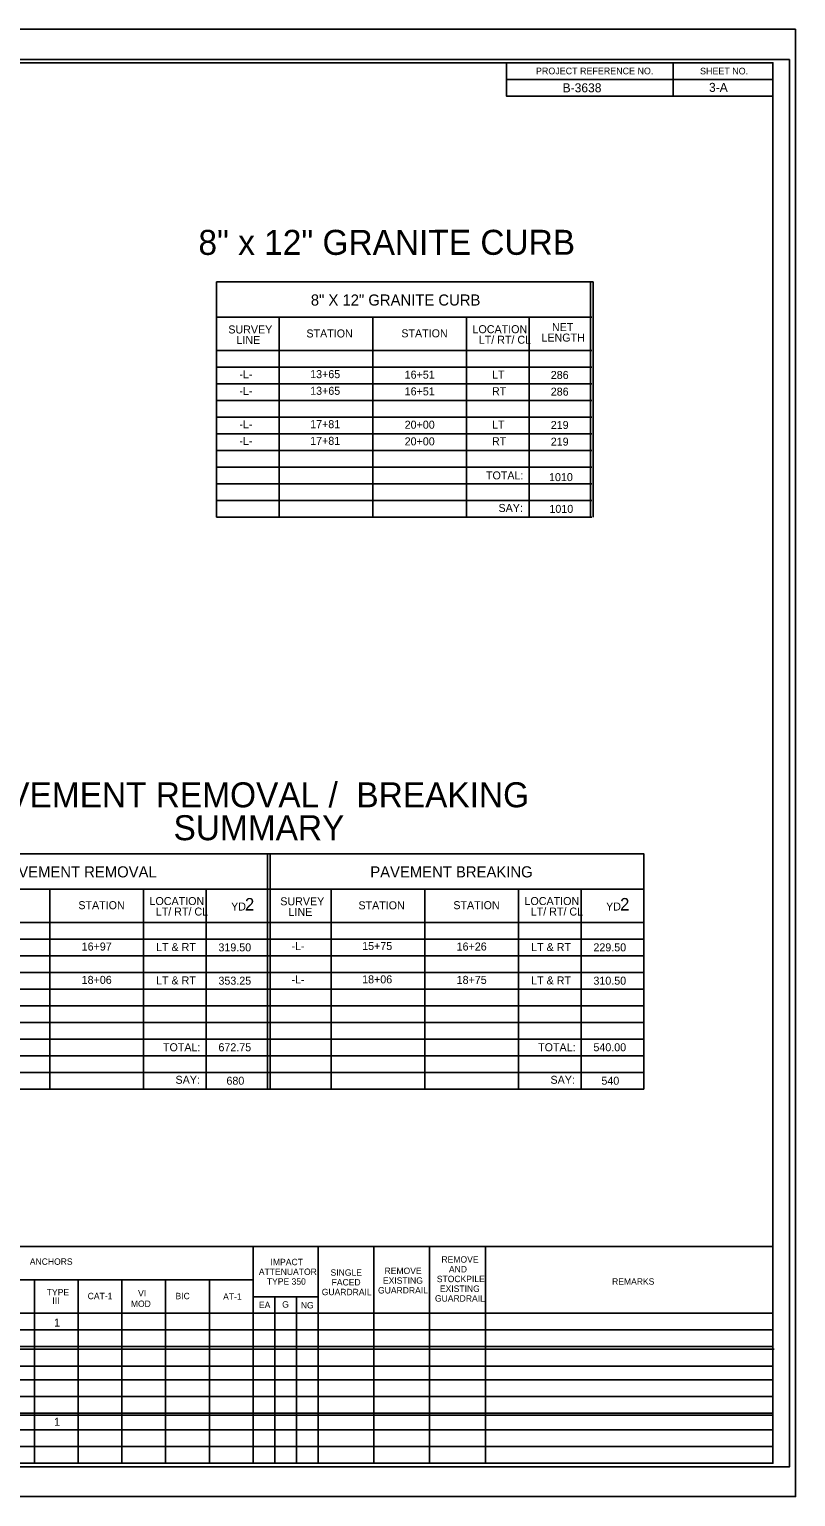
# Model space of a CAD drawing. Extents: x 1932260 to 1932428, y 647261 to 647371.
# Drawn here: x 1932370.6 to 1932428.1, y 647261 to 647371 of the extents above; entities that cross this region are included whole.
import ezdxf

# ---------------------------------------------------------------- set-up
doc = ezdxf.new("R2010")
doc.units = 0
for name, color, linetype in [('Sheet Cutting Line CELL', 7, 'Continuous'), ('Sheet Data Field CELL', 7, 'Continuous'), ('Sheet Plot Border Inside CELL', 7, 'Continuous'), ('Sheet Plot Border Outside CELL', 7, 'Continuous'), ('Sheet Summary Combination CELL', 7, 'Continuous'), ('Sheet Summary Combination Grid CELL', 7, 'Continuous'), ('Sheet Summary Earthwork CELL', 7, 'Continuous')]:
    doc.layers.add(name, color=color, linetype=linetype)

msp = doc.modelspace()

# ---------------------------------------------------------------- linework, layer by layer
at = {"layer": 'Sheet Cutting Line CELL'}
for p, q in [((1932428.13, 647371.04), (1932259.73, 647371.04)), ((1932259.73, 647261.04), (1932428.13, 647261.04))]:
    msp.add_line(p, q, dxfattribs=at)
at = {"layer": 'Sheet Plot Border Inside CELL'}
msp.add_lwpolyline([(1932427.68, 647368.79), (1932261.03, 647368.79), (1932261.03, 647263.28), (1932427.68, 647263.28)], close=True, dxfattribs=at)
at = {"layer": 'Sheet Plot Border Outside CELL'}
msp.add_lwpolyline([(1932428.13, 647371.04), (1932259.73, 647371.04), (1932259.73, 647261.04), (1932428.13, 647261.04)], close=True, dxfattribs=at)
at = {"layer": 'Sheet Summary Combination CELL'}
for p, q in [((1932428.13, 647371.04), (1932428.13, 647371.04)), ((1932427.68, 647368.79), (1932427.68, 647368.79)), ((1932398.82, 647349.46), (1932398.82, 647349.46)), ((1932399.44, 647349.45), (1932399.44, 647349.45)), ((1932400.35, 647349.47), (1932400.35, 647349.47)), ((1932400.91, 647349.46), (1932400.91, 647349.46)), ((1932374.59, 647306.59), (1932374.59, 647306.59)), ((1932375.21, 647306.58), (1932375.21, 647306.58)), ((1932376.12, 647306.6), (1932376.12, 647306.6)), ((1932376.68, 647306.59), (1932376.68, 647306.59)), ((1932402.72, 647306.59), (1932402.72, 647306.59)), ((1932403.35, 647306.58), (1932403.35, 647306.58)), ((1932404.25, 647306.6), (1932404.25, 647306.6)), ((1932404.81, 647306.59), (1932404.81, 647306.59))]:
    msp.add_line(p, q, dxfattribs=at)
at = {"layer": 'Sheet Summary Combination Grid CELL'}
for p, q in [((1932412.73, 647352.11), (1932412.73, 647334.46)), ((1932412.73, 647352.11), (1932412.93, 647352.11)), ((1932412.93, 647352.11), (1932412.93, 647334.46)), ((1932384.69, 647349.46), (1932412.83, 647349.46)), ((1932384.69, 647349.46), (1932384.69, 647334.46)), ((1932389.38, 647349.46), (1932389.38, 647334.46)), ((1932396.42, 647349.46), (1932396.42, 647334.46)), ((1932403.45, 647349.46), (1932403.45, 647334.46)), ((1932408.14, 647349.46), (1932408.14, 647334.46)), ((1932384.69, 647346.96), (1932412.83, 647346.96)), ((1932384.69, 647345.71), (1932412.83, 647345.71)), ((1932384.69, 647344.46), (1932412.83, 647344.46)), ((1932384.69, 647343.21), (1932412.83, 647343.21)), ((1932384.69, 647341.96), (1932412.83, 647341.96)), ((1932384.69, 647340.71), (1932412.83, 647340.71)), ((1932384.69, 647339.46), (1932412.83, 647339.46)), ((1932384.69, 647338.21), (1932412.83, 647338.21)), ((1932384.69, 647336.96), (1932412.83, 647336.96)), ((1932384.69, 647335.71), (1932412.83, 647335.71)), ((1932384.69, 647334.46), (1932412.83, 647334.46)), ((1932388.5, 647309.24), (1932388.5, 647291.59)), ((1932388.5, 647309.24), (1932388.7, 647309.24)), ((1932388.7, 647309.24), (1932388.7, 647291.59)), ((1932360.46, 647306.59), (1932388.6, 647306.59)), ((1932372.19, 647306.59), (1932372.19, 647291.59)), ((1932379.22, 647306.59), (1932379.22, 647291.59)), ((1932383.91, 647306.59), (1932383.91, 647291.59)), ((1932388.6, 647306.59), (1932416.73, 647306.59)), ((1932393.29, 647306.59), (1932393.29, 647291.59)), ((1932400.32, 647306.59), (1932400.32, 647291.59)), ((1932407.35, 647306.59), (1932407.35, 647291.59)), ((1932412.04, 647306.59), (1932412.04, 647291.59)), ((1932416.73, 647306.59), (1932416.73, 647291.59)), ((1932360.46, 647304.09), (1932388.6, 647304.09)), ((1932388.6, 647304.09), (1932416.73, 647304.09)), ((1932360.46, 647302.84), (1932388.6, 647302.84)), ((1932388.6, 647302.84), (1932416.73, 647302.84)), ((1932360.46, 647301.59), (1932388.6, 647301.59)), ((1932388.6, 647301.59), (1932416.73, 647301.59)), ((1932360.46, 647300.34), (1932388.6, 647300.34)), ((1932388.6, 647300.34), (1932416.73, 647300.34)), ((1932360.46, 647299.09), (1932388.6, 647299.09)), ((1932388.6, 647299.09), (1932416.73, 647299.09)), ((1932360.46, 647297.84), (1932388.6, 647297.84)), ((1932388.6, 647297.84), (1932416.73, 647297.84)), ((1932360.46, 647296.59), (1932388.6, 647296.59)), ((1932388.6, 647296.59), (1932416.73, 647296.59)), ((1932360.46, 647295.34), (1932388.6, 647295.34)), ((1932388.6, 647295.34), (1932416.73, 647295.34)), ((1932360.46, 647294.09), (1932388.6, 647294.09)), ((1932388.6, 647294.09), (1932416.73, 647294.09)), ((1932360.46, 647292.84), (1932388.6, 647292.84)), ((1932388.6, 647292.84), (1932416.73, 647292.84)), ((1932360.46, 647291.59), (1932388.6, 647291.59)), ((1932388.6, 647291.59), (1932416.73, 647291.59)), ((1932276.43, 647279.79), (1932426.43, 647279.79)), ((1932387.43, 647279.79), (1932387.43, 647263.54)), ((1932392.31, 647279.79), (1932392.31, 647263.54)), ((1932396.49, 647279.79), (1932396.49, 647263.54)), ((1932400.67, 647279.79), (1932400.67, 647263.54)), ((1932404.86, 647279.79), (1932404.86, 647263.54)), ((1932387.43, 647277.29), (1932339.71, 647277.29)), ((1932371.02, 647277.29), (1932371.02, 647263.54)), ((1932374.3, 647277.29), (1932374.3, 647263.54)), ((1932377.58, 647277.29), (1932377.58, 647263.54)), ((1932380.87, 647277.29), (1932380.87, 647263.54)), ((1932384.15, 647277.29), (1932384.15, 647263.54)), ((1932387.43, 647276.01), (1932392.29, 647276.01)), ((1932389.05, 647276.01), (1932389.06, 647263.54)), ((1932390.69, 647276.01), (1932390.69, 647263.54)), ((1932276.43, 647274.79), (1932426.43, 647274.79)), ((1932276.43, 647273.54), (1932426.43, 647273.54)), ((1932276.43, 647272.29), (1932426.43, 647272.29)), ((1932276.51, 647272.09), (1932426.51, 647272.09)), ((1932276.43, 647270.83), (1932426.43, 647270.83)), ((1932276.43, 647269.79), (1932426.43, 647269.79)), ((1932276.43, 647268.54), (1932426.43, 647268.54)), ((1932276.43, 647267.29), (1932426.43, 647267.29)), ((1932276.43, 647267.14), (1932426.43, 647267.14)), ((1932276.43, 647266.04), (1932426.43, 647266.04)), ((1932276.43, 647264.79), (1932426.43, 647264.79))]:
    msp.add_line(p, q, dxfattribs=at)
for points in [[(1932412.73, 647349.46), (1932384.69, 647349.46), (1932384.69, 647352.11), (1932412.73, 647352.11)], [(1932388.5, 647306.59), (1932360.46, 647306.59), (1932360.46, 647309.24), (1932388.5, 647309.24)], [(1932416.73, 647306.59), (1932388.7, 647306.59), (1932388.7, 647309.24), (1932416.73, 647309.24)]]:
    msp.add_lwpolyline(points, close=True, dxfattribs=at)
at = {"layer": 'Sheet Summary Earthwork CELL'}
for p, q in [((1932418.93, 647368.53), (1932418.93, 647366.03)), ((1932406.43, 647367.28), (1932426.43, 647367.28))]:
    msp.add_line(p, q, dxfattribs=at)
for points in [[(1932426.43, 647368.54), (1932276.43, 647368.54), (1932276.43, 647263.54), (1932426.43, 647263.54)], [(1932406.43, 647368.54), (1932426.43, 647368.54), (1932426.43, 647366.03), (1932406.43, 647366.03)]]:
    msp.add_lwpolyline(points, close=True, dxfattribs=at)

# ---------------------------------------------------------------- texts
at = {"layer": 'Sheet Data Field CELL'}
for s, p in [('B-3638', (1932410.65, 647366.32)), ('3-A', (1932421.63, 647366.35))]:
    msp.add_text(s, height=0.675, dxfattribs=at).set_placement(p)
at = {"layer": 'Sheet Summary Combination CELL'}
for s, height, p in [('8" x 12" GRANITE CURB', 1.875, (1932383.33, 647354.13)), ('8" X 12" GRANITE CURB', 0.8319, (1932391.76, 647350.33)), ('PAVEMENT REMOVAL /  BREAKING', 1.875, (1932365.64, 647312.71)), ('SUMMARY', 1.875, (1932381.46, 647310.25)), ('PAVEMENT REMOVAL', 0.8319, (1932368.33, 647307.46)), ('PAVEMENT BREAKING', 0.8319, (1932396.22, 647307.46))]:
    msp.add_text(s, height=height, rotation=0.0119, dxfattribs=at).set_placement(p)
for s, height, p in [('SURVEY', 0.6, (1932385.57, 647348.24)), ('LINE', 0.6, (1932386.18, 647347.45)), ('STATION', 0.6, (1932391.43, 647347.94)), ('STATION', 0.6, (1932398.55, 647347.95)), ('LOCATION', 0.6, (1932403.89, 647348.26)), ('LT/ RT/ CL', 0.6, (1932404.36, 647347.47)), ('TOTAL:', 0.6, (1932404.9, 647337.3)), ('SAY:', 0.6, (1932405.84, 647334.86)), ('STATION', 0.6, (1932374.32, 647305.08)), ('LOCATION', 0.6, (1932379.66, 647305.39)), ('LT/ RT/ CL', 0.6, (1932380.13, 647304.6)), ('SURVEY', 0.6, (1932389.47, 647305.37)), ('LINE', 0.6, (1932390.09, 647304.58)), ('STATION', 0.6, (1932395.33, 647305.07)), ('STATION', 0.6, (1932402.45, 647305.08)), ('LOCATION', 0.6, (1932407.79, 647305.39)), ('LT/ RT/ CL', 0.6, (1932408.26, 647304.6)), ('TOTAL:', 0.6, (1932380.67, 647294.43)), ('TOTAL:', 0.6, (1932408.81, 647294.43)), ('SAY:', 0.6, (1932381.61, 647291.99)), ('SAY:', 0.6, (1932409.74, 647291.99)), ('ANCHORS', 0.48, (1932370.68, 647278.42)), ('IMPACT', 0.48, (1932388.74, 647278.39)), ('REMOVE', 0.48, (1932401.56, 647278.58)), ('ATTENUATOR', 0.48, (1932387.86, 647277.66)), ('TYPE 350', 0.48, (1932388.46, 647276.93)), ('SINGLE', 0.48, (1932393.24, 647277.6)), ('EXISTING', 0.48, (1932397.17, 647277)), ('REMOVE', 0.48, (1932397.29, 647277.73)), ('STOCKPILE', 0.48, (1932401.21, 647277.12)), ('AND', 0.48, (1932402.12, 647277.85)), ('REMARKS', 0.48, (1932414.36, 647276.93)), ('TYPE', 0.48, (1932371.95, 647276.12)), ('CAT-1', 0.48, (1932375.02, 647275.84)), ('VI', 0.48, (1932378.8, 647276.05)), ('BIC', 0.48, (1932381.61, 647275.84)), ('GUARDRAIL', 0.48, (1932392.58, 647276.14)), ('FACED', 0.48, (1932393.32, 647276.87)), ('GUARDRAIL', 0.48, (1932396.8, 647276.27)), ('EXISTING', 0.48, (1932401.44, 647276.39)), ('III', 0.48, (1932372.37, 647275.49)), ('MOD', 0.48, (1932378.26, 647275.26)), ('AT-1', 0.48, (1932385.18, 647275.8)), ('EA', 0.48, (1932387.87, 647275.17)), ('G', 0.48, (1932389.61, 647275.21)), ('NG', 0.48, (1932391.01, 647275.15)), ('GUARDRAIL', 0.48, (1932401.07, 647275.66))]:
    msp.add_text(s, height=height, dxfattribs=at).set_placement(p)
at = {"layer": 'Sheet Summary Combination Grid CELL'}
for s, height, p in [('NET', 0.6, (1932409.85, 647348.42)), ('LENGTH', 0.6, (1932409.06, 647347.63)), ('YD', 0.6, (1932385.78, 647304.98)), ('2', 0.938, (1932386.82, 647304.98)), ('YD', 0.6, (1932413.91, 647304.98)), ('2', 0.938, (1932414.96, 647304.98))]:
    msp.add_text(s, height=height, dxfattribs=at).set_placement(p)
at = {"layer": 'Sheet Summary Earthwork CELL'}
for s, height, p in [('PROJECT REFERENCE NO.', 0.5, (1932408.65, 647367.67)), ('SHEET NO.', 0.5, (1932420.96, 647367.66)), ('-L-', 0.6, (1932386.4, 647344.88)), ('13+65', 0.6, (1932391.71, 647344.89)), ('16+51', 0.6, (1932398.8, 647344.85)), ('LT', 0.6, (1932405.35, 647344.86)), ('286', 0.6, (1932409.76, 647344.83)), ('-L-', 0.6, (1932386.4, 647343.63)), ('13+65', 0.6, (1932391.71, 647343.64)), ('16+51', 0.6, (1932398.8, 647343.6)), ('RT', 0.6, (1932405.35, 647343.61)), ('286', 0.6, (1932409.76, 647343.58)), ('-L-', 0.6, (1932386.4, 647341.13)), ('17+81', 0.6, (1932391.71, 647341.14)), ('20+00', 0.6, (1932398.8, 647341.1)), ('LT', 0.6, (1932405.35, 647341.11)), ('219', 0.6, (1932409.76, 647341.08)), ('-L-', 0.6, (1932386.4, 647339.88)), ('17+81', 0.6, (1932391.71, 647339.89)), ('20+00', 0.6, (1932398.8, 647339.85)), ('RT', 0.6, (1932405.35, 647339.86)), ('219', 0.6, (1932409.76, 647339.83)), ('1010', 0.6, (1932409.63, 647337.17)), ('1010', 0.6, (1932409.66, 647334.79)), ('16+97', 0.6, (1932374.57, 647301.98)), ('LT & RT', 0.6, (1932380.15, 647301.94)), ('319.50', 0.6, (1932384.83, 647301.92)), ('-L-', 0.6, (1932390.31, 647302.01)), ('15+75', 0.6, (1932395.61, 647302.02)), ('16+26', 0.6, (1932402.7, 647301.98)), ('LT & RT', 0.6, (1932408.29, 647301.94)), ('229.50', 0.6, (1932412.96, 647301.92)), ('18+06', 0.6, (1932374.57, 647299.48)), ('LT & RT', 0.6, (1932380.15, 647299.44)), ('353.25', 0.6, (1932384.83, 647299.42)), ('-L-', 0.6, (1932390.31, 647299.51)), ('18+06', 0.6, (1932395.61, 647299.52)), ('18+75', 0.6, (1932402.7, 647299.48)), ('LT & RT', 0.6, (1932408.29, 647299.44)), ('310.50', 0.6, (1932412.96, 647299.42)), ('672.75', 0.6, (1932384.83, 647294.43)), ('540.00', 0.6, (1932412.96, 647294.43)), ('680', 0.6, (1932385.43, 647291.92)), ('540', 0.6, (1932413.56, 647291.92)), ('1', 0.6, (1932372.5, 647273.79)), ('1', 0.6, (1932372.5, 647266.35))]:
    msp.add_text(s, height=height, dxfattribs=at).set_placement(p)

doc.saveas('drawing.dxf')
